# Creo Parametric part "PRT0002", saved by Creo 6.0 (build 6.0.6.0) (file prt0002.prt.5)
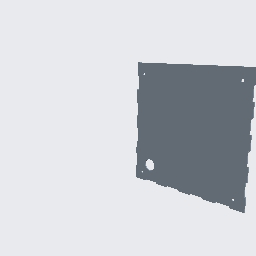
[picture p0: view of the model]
Units: Inch lbm Second (Pro/E Default); INCH, POUND, SECS

Created from: INLBS_PART_SOLID.PRT

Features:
  1. datum plane "RIGHT"
  2. datum plane "TOP"
  3. datum plane "FRONT"
  4. coordinate system
  5. sketch "Sketch 1"
  6. extrusion "Extrude 1"
  7. sketch "Sketch 2"
  8. extruded cut "Extrude 2"
  9. sketch "Sketch 3"
  10. extruded cut "Extrude 3"

Surfaces: 54 plane, 5 cylinder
